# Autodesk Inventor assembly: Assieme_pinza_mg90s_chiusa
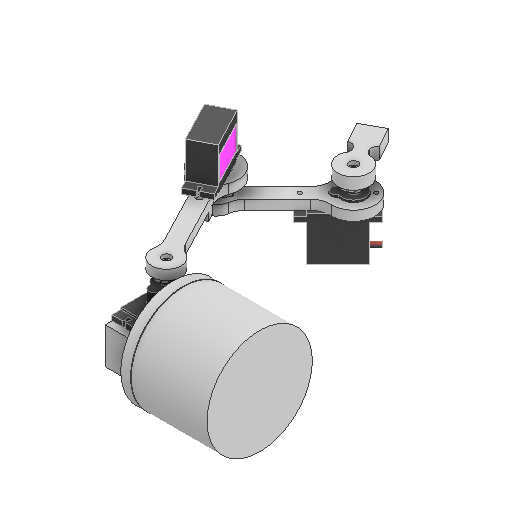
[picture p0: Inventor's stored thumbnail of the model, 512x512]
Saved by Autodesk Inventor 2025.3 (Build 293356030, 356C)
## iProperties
Created: 2026-03
Part Number: Assieme_pinza_mg90s_chiusa
Document SubType Name: Assembly
Designer: Ryzen5700u
Sending System: Autodesk Inventor 2025
Preprocessor: ST-DEVELOPER v20
Title: Assieme_pinza_mg90s_chiusa.stp
Author: R5800u
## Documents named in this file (8)
- C:\Users\R5800u\Desktop\robot eco\Assieme_pinza_mg90s_chiusa\Assieme_pinza_mg90s_chiusa.iam
- C:\Users\R5800u\Desktop\robot eco\Assieme_pinza_mg90s_chiusa\MG90_ldb.ipt
- C:\Users\R5800u\Desktop\robot eco\Assieme_pinza_mg90s_chiusa\MG90S ARM 2x.ipt
- C:\Users\R5800u\Desktop\robot eco\braccio_1.ipt
- C:\Users\R5800u\Desktop\robot eco\braccio_3.ipt
- C:\Users\R5800u\Desktop\robot eco\braccio_2.ipt
- C:\Users\R5800u\Desktop\robot eco\base.ipt
- C:\Users\R5800u\Desktop\robot eco\base_cilindro.ipt
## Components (13 placed, 7 different names)
1. MG90_ldb:1 — Rotazionale:1, Coincidente:1, Allineato:1
2. MG90S ARM 2x:1 — Rotazionale:1, Coincidente:2, Angolo:2
3. braccio_1:1 — Coincidente:1, Coincidente:2, Coincidente:3, Angolo:1, Coincidente:4, Angolo:2
4. MG90_ldb:2 — Coincidente:3, Angolo:1, Coincidente:4, Rotazionale:2, Coincidente:11
5. MG90S ARM 2x:2 — Rotazionale:2, Coincidente:12, Angolo:8
6. MG90_ldb:3 — Rotazionale:4, Coincidente:7, Coincidente:13, Coincidente:14, Angolo:9
7. braccio_3:1 — Coincidente:7, Coincidente:8, Angolo:7
8. MG90S ARM 2x:3 — Rotazionale:4, Coincidente:8, Angolo:7
9. base:1 — Allineato:1, Coincidente:9, Coincidente:10, Coincidente:15, Angolo:10
10. MG90_ldb:4 — Rotazionale:5, Coincidente:10, Angolo:5, Coincidente:17, Angolo:10, Coincidente:18
11. MG90S ARM 2x:4 — Rotazionale:5, Coincidente:9, Angolo:5
12. base_cilindro:1 — Coincidente:15, Coincidente:17, Coincidente:18, Allineato:3
13. braccio_2:1 — Coincidente:11, Coincidente:12, Angolo:8, Coincidente:13, Coincidente:14, Angolo:9
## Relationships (28: Mate 15, Angle 7, RevoluteJoint 4, Flush 2)
- Rotazionale:1 [RevoluteJoint]: MG90_ldb:1 ↔ MG90S ARM 2x:1
- Coincidente:1 [Mate]: MG90_ldb:1 ↔ braccio_1:1
- Coincidente:2 [Mate]: MG90S ARM 2x:1 ↔ braccio_1:1
- Coincidente:3 [Mate]: braccio_1:1 ↔ MG90_ldb:2
- Angolo:1 [Angle]: braccio_1:1 ↔ MG90_ldb:2
- Coincidente:4 [Mate]: braccio_1:1 ↔ MG90_ldb:2
- Angolo:2 [Angle]: MG90S ARM 2x:1 ↔ braccio_1:1
- Rotazionale:2 [RevoluteJoint]: MG90_ldb:2 ↔ MG90S ARM 2x:2
- Rotazionale:4 [RevoluteJoint]: MG90_ldb:3 ↔ MG90S ARM 2x:3
- Coincidente:7 [Mate]: MG90_ldb:3 ↔ braccio_3:1
- Coincidente:8 [Mate]: braccio_3:1 ↔ MG90S ARM 2x:3
- Allineato:1 [Flush]: MG90_ldb:1 ↔ base:1
- Rotazionale:5 [RevoluteJoint]: MG90_ldb:4 ↔ MG90S ARM 2x:4
- Coincidente:9 [Mate]: base:1 ↔ MG90S ARM 2x:4
- Coincidente:10 [Mate]: base:1 ↔ MG90_ldb:4
- Angolo:5 [Angle]: MG90_ldb:4 ↔ MG90S ARM 2x:4
- Angolo:7 [Angle]: braccio_3:1 ↔ MG90S ARM 2x:3
- Coincidente:11 [Mate]: MG90_ldb:2 ↔ braccio_2:1
- Coincidente:12 [Mate]: MG90S ARM 2x:2 ↔ braccio_2:1
- Angolo:8 [Angle]: MG90S ARM 2x:2 ↔ braccio_2:1
- Coincidente:13 [Mate]: MG90_ldb:3 ↔ braccio_2:1
- Coincidente:14 [Mate]: MG90_ldb:3 ↔ braccio_2:1
- Angolo:9 [Angle]: MG90_ldb:3 ↔ braccio_2:1
- Coincidente:15 [Mate]: base:1 ↔ base_cilindro:1
- Coincidente:17 [Mate]: MG90_ldb:4 ↔ base_cilindro:1
- Angolo:10 [Angle]: base:1 ↔ MG90_ldb:4
- Coincidente:18 [Mate]: MG90_ldb:4 ↔ base_cilindro:1
- Allineato:3 [Flush]: base_cilindro:1
